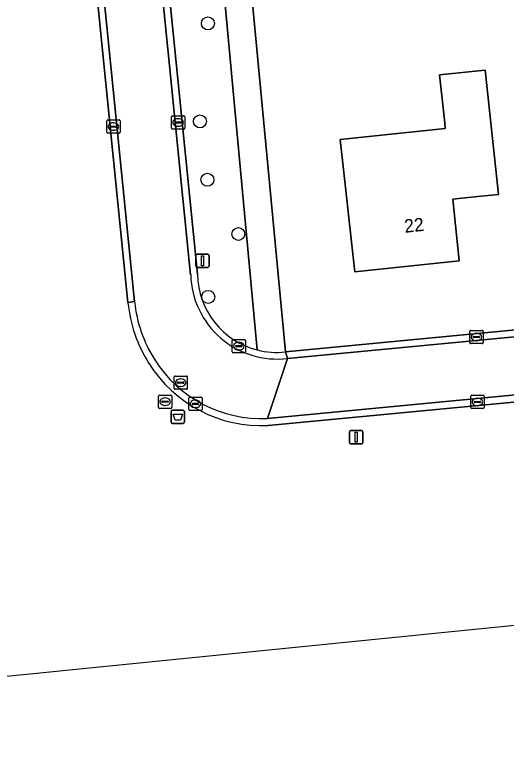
# Model space of a CAD drawing. Extents: x 162661 to 163484, y 380247 to 381230.
# Drawn here: x 162921.2 to 162958.2, y 380249 to 380305.3 of the extents above; entities that cross this region are included whole.
import ezdxf

# ---------------------------------------------------------------- set-up
doc = ezdxf.new("R2010")
doc.units = 0
for name, color, linetype in [('IMGEO_Afvalbak', 7, 'Continuous'), ('IMGEO_Boom', 7, 'Continuous'), ('IMGEO_Erf', 7, 'Continuous'), ('IMGEO_Gemengd_bos', 7, 'Continuous'), ('IMGEO_Groenvoorziening', 7, 'Continuous'), ('IMGEO_Kolk', 7, 'Continuous'), ('IMGEO_Lichtmast', 7, 'Continuous'), ('IMGEO_Pand', 7, 'Continuous'), ('IMGEO_Pand_nummerreeks', 7, 'Continuous'), ('IMGEO_Rijbaan_lokaal_gesloten', 7, 'Continuous'), ('IMGEO_Rijbaan_lokaal_open', 7, 'Continuous'), ('IMGEO_Rioolput', 7, 'Continuous'), ('IMGEO_Voetpad_open', 7, 'Continuous')]:
    doc.layers.add(name, color=color, linetype=linetype)

msp = doc.modelspace()

# ---------------------------------------------------------------- linework, layer by layer
at = {"layer": 'IMGEO_Afvalbak'}
for p, q in [((162932.953, 380274.682), (162932.953, 380275.482)), ((162932.953, 380275.482), (162932.953, 380274.682)), ((162933.053, 380275.582), (162933.843, 380275.582)), ((162933.843, 380275.582), (162933.053, 380275.582)), ((162933.943, 380275.482), (162933.943, 380274.682)), ((162933.943, 380274.682), (162933.943, 380275.482)), ((162933.843, 380274.582), (162933.053, 380274.582)), ((162933.053, 380274.582), (162933.843, 380274.582))]:
    msp.add_line(p, q, dxfattribs=at)
msp.add_lwpolyline([(162933.096, 380275.296), (162933.8, 380275.296), (162933.651, 380274.826), (162933.245, 380274.826), (162933.096, 380275.296)], dxfattribs=at)
for centre, start, end in [((162933.053, 380275.482), 90, 180), ((162933.053, 380275.482), 90, 180), ((162933.843, 380275.482), 0, 90), ((162933.843, 380275.482), 360, 90), ((162933.053, 380274.682), 180, 270), ((162933.053, 380274.682), 180, 270), ((162933.843, 380274.682), 270, 0), ((162933.843, 380274.682), 270, 0)]:
    msp.add_arc(centre, 0.1, start, end, dxfattribs=at)
at = {"layer": 'IMGEO_Boom'}
for centre in [(162935.717, 380304.705), (162935.116, 380297.327), (162935.674, 380292.93), (162938.006, 380288.849), (162935.738, 380284.117)]:
    msp.add_circle(centre, 0.489, dxfattribs=at)
at = {"layer": 'IMGEO_Erf'}
for points in [[(163025.144, 380326.321), (163024.481, 380337.057), (163009.587, 380336.032), (163009.593, 380335.742), (163006.725, 380335.529), (163006.73, 380335.638), (163003.141, 380335.415), (163000, 380335.199), (162936.743, 380330.858), (162941.559, 380279.973), (163028.489, 380288.289)], [(162953.584, 380296.784), (162953.537, 380297.227), (162953.157, 380300.828), (162956.592, 380301.19), (162956.715, 380300.025), (162957.582, 380291.83), (162955.998, 380291.663), (162954.146, 380291.468), (162954.636, 380286.834), (162946.769, 380286.004), (162945.669, 380295.974)]]:
    msp.add_lwpolyline(points, close=True, dxfattribs=at)
at = {"layer": 'IMGEO_Gemengd_bos'}
for points in [[(162929.701, 380283.683), (162923.037, 380349.9)], [(162854.54, 380248.952), (162974.798, 380261.009), (163143.705, 380286.144), (163143.702, 380286.229), (163143.673, 380287.21), (163143.37, 380289.928), (163142.476, 380293.987)], [(163020.214, 380282.048), (162940.242, 380274.439)]]:
    msp.add_lwpolyline(points, dxfattribs=at)
for centre, radius, start, end in [((162939.967, 380284.67), 10.314, 185.4904, 212.594), ((162939.73, 380284.389), 9.963, 211.9674, 272.9458)]:
    msp.add_arc(centre, radius, start, end, dxfattribs=at)
at = {"layer": 'IMGEO_Groenvoorziening'}
msp.add_lwpolyline([(162939.426, 380280.12), (162934.723, 380330.738), (162930.435, 380330.4), (162934.938, 380285.824)], dxfattribs=at)
msp.add_arc((162940.899, 380285.896), 5.961, 180.6944, 255.6981, dxfattribs=at)
at = {"layer": 'IMGEO_Kolk'}
for p, q in [((162928.102, 380296.509), (162928.102, 380297.361)), ((162928.177, 380297.435), (162929.029, 380297.435)), ((162929.103, 380297.361), (162929.103, 380296.509)), ((162932.971, 380296.82), (162932.971, 380297.672)), ((162933.046, 380297.746), (162933.898, 380297.746)), ((162933.273, 380297.289), (162933.671, 380297.289)), ((162933.459, 380297.526), (162933.484, 380297.526)), ((162933.972, 380297.672), (162933.972, 380296.82)), ((162928.361, 380296.929), (162928.361, 380296.941)), ((162928.799, 380296.892), (162928.401, 380296.892)), ((162928.404, 380296.978), (162928.802, 380296.978)), ((162928.59, 380297.215), (162928.615, 380297.215)), ((162928.845, 380296.941), (162928.845, 380296.929)), ((162933.898, 380296.746), (162933.046, 380296.746)), ((162933.23, 380297.24), (162933.23, 380297.252)), ((162933.668, 380297.203), (162933.27, 380297.203)), ((162933.482, 380296.966), (162933.457, 380296.966)), ((162933.714, 380297.252), (162933.714, 380297.24)), ((162929.029, 380296.435), (162928.177, 380296.435)), ((162928.613, 380296.655), (162928.588, 380296.655)), ((162955.427, 380280.67), (162955.427, 380281.522)), ((162955.502, 380281.596), (162956.354, 380281.596)), ((162956.428, 380281.522), (162956.428, 380280.67)), ((162955.686, 380281.09), (162955.686, 380281.102)), ((162956.124, 380281.053), (162955.726, 380281.053)), ((162955.729, 380281.139), (162956.127, 380281.139)), ((162955.915, 380281.376), (162955.94, 380281.376)), ((162956.17, 380281.102), (162956.17, 380281.09)), ((162937.543, 380279.981), (162937.543, 380280.833)), ((162937.618, 380280.907), (162938.47, 380280.907)), ((162937.802, 380280.401), (162937.802, 380280.413)), ((162938.24, 380280.364), (162937.842, 380280.364)), ((162937.845, 380280.45), (162938.243, 380280.45)), ((162938.031, 380280.687), (162938.056, 380280.687)), ((162938.286, 380280.413), (162938.286, 380280.401)), ((162938.544, 380280.833), (162938.544, 380279.981)), ((162956.354, 380280.596), (162955.502, 380280.596)), ((162955.938, 380280.816), (162955.913, 380280.816)), ((162938.47, 380279.907), (162937.618, 380279.907)), ((162938.054, 380280.127), (162938.029, 380280.127)), ((162934.271, 380275.635), (162934.271, 380276.487)), ((162934.346, 380276.561), (162935.198, 380276.561)), ((162935.272, 380276.487), (162935.272, 380275.635)), ((162955.498, 380275.78), (162955.498, 380276.632)), ((162955.573, 380276.706), (162956.425, 380276.706)), ((162955.986, 380276.486), (162956.011, 380276.486)), ((162956.499, 380276.632), (162956.499, 380275.78)), ((162934.53, 380276.055), (162934.53, 380276.067)), ((162934.968, 380276.018), (162934.57, 380276.018)), ((162934.573, 380276.104), (162934.971, 380276.104)), ((162934.759, 380276.341), (162934.784, 380276.341)), ((162935.014, 380276.067), (162935.014, 380276.055)), ((162955.757, 380276.2), (162955.757, 380276.212)), ((162956.195, 380276.163), (162955.797, 380276.163)), ((162955.8, 380276.249), (162956.198, 380276.249)), ((162956.009, 380275.926), (162955.984, 380275.926)), ((162956.241, 380276.212), (162956.241, 380276.2)), ((162935.198, 380275.561), (162934.346, 380275.561)), ((162934.782, 380275.781), (162934.757, 380275.781)), ((162956.425, 380275.706), (162955.573, 380275.706))]:
    msp.add_line(p, q, dxfattribs=at)
for points in [[(162928.102, 380296.509), (162928.102, 380297.361)], [(162928.177, 380297.435), (162929.029, 380297.435)], [(162929.103, 380297.361), (162929.103, 380296.509)], [(162932.971, 380296.82), (162932.971, 380297.672)], [(162933.046, 380297.746), (162933.898, 380297.746)], [(162933.972, 380297.672), (162933.972, 380296.82)], [(162933.898, 380296.746), (162933.046, 380296.746)], [(162929.029, 380296.435), (162928.177, 380296.435)], [(162955.427, 380280.67), (162955.427, 380281.522)], [(162955.502, 380281.596), (162956.354, 380281.596)], [(162956.428, 380281.522), (162956.428, 380280.67)], [(162937.543, 380279.981), (162937.543, 380280.833)], [(162937.618, 380280.907), (162938.47, 380280.907)], [(162938.544, 380280.833), (162938.544, 380279.981)], [(162956.354, 380280.596), (162955.502, 380280.596)], [(162938.47, 380279.907), (162937.618, 380279.907)], [(162934.271, 380275.635), (162934.271, 380276.487)], [(162934.346, 380276.561), (162935.198, 380276.561)], [(162935.272, 380276.487), (162935.272, 380275.635)], [(162955.498, 380275.78), (162955.498, 380276.632)], [(162955.573, 380276.706), (162956.425, 380276.706)], [(162956.499, 380276.632), (162956.499, 380275.78)], [(162935.198, 380275.561), (162934.346, 380275.561)], [(162956.425, 380275.706), (162955.573, 380275.706)]]:
    msp.add_lwpolyline(points, dxfattribs=at)
for centre, radius, start, end in [((162928.179, 380297.359), 0.0765, 91.552, 178.448), ((162928.179, 380297.359), 0.0765, 91.552, 178.448), ((162929.027, 380297.359), 0.0765, 1.552, 88.448), ((162929.027, 380297.359), 0.0765, 1.552, 88.448), ((162933.048, 380297.67), 0.0765, 91.552, 178.448), ((162933.048, 380297.67), 0.0765, 91.552, 178.448), ((162933.27, 380297.249), 0.0403, 85.8775, 175.7526), ((162933.675, 380297.251), 0.0386, 1.7309, 96.639), ((162933.896, 380297.67), 0.0765, 1.552, 88.448), ((162933.896, 380297.67), 0.0765, 1.552, 88.448), ((162928.401, 380296.938), 0.0403, 85.8775, 175.7526), ((162928.398, 380296.928), 0.0366, 178.938, 274.7102), ((162928.802, 380296.935), 0.043, 264.8664, 352.4533), ((162928.806, 380296.94), 0.0386, 1.7309, 96.639), ((162933.048, 380296.822), 0.0765, 181.552, 268.448), ((162933.048, 380296.822), 0.0765, 181.552, 268.448), ((162933.267, 380297.239), 0.0366, 178.938, 274.7102), ((162933.671, 380297.246), 0.043, 264.8664, 352.4533), ((162933.896, 380296.822), 0.0765, 271.552, 358.448), ((162933.896, 380296.822), 0.0765, 271.552, 358.448), ((162928.179, 380296.511), 0.0765, 181.552, 268.448), ((162928.179, 380296.511), 0.0765, 181.552, 268.448), ((162929.027, 380296.511), 0.0765, 271.552, 358.448), ((162929.027, 380296.511), 0.0765, 271.552, 358.448), ((162955.504, 380281.52), 0.0765, 91.552, 178.448), ((162955.504, 380281.52), 0.0765, 91.552, 178.448), ((162956.352, 380281.52), 0.0765, 1.552, 88.448), ((162956.352, 380281.52), 0.0765, 1.552, 88.448), ((162955.726, 380281.099), 0.0403, 85.8775, 175.7526), ((162955.723, 380281.089), 0.0366, 178.938, 274.7102), ((162956.127, 380281.096), 0.043, 264.8664, 352.4533), ((162956.131, 380281.101), 0.0386, 1.7309, 96.639), ((162937.62, 380280.831), 0.0765, 91.552, 178.448), ((162937.62, 380280.831), 0.0765, 91.552, 178.448), ((162937.842, 380280.41), 0.0403, 85.8775, 175.7526), ((162937.839, 380280.4), 0.0366, 178.938, 274.7102), ((162938.243, 380280.407), 0.043, 264.8664, 352.4533), ((162938.247, 380280.412), 0.0386, 1.7309, 96.639), ((162938.468, 380280.831), 0.0765, 1.552, 88.448), ((162938.468, 380280.831), 0.0765, 1.552, 88.448), ((162955.504, 380280.672), 0.0765, 181.552, 268.448), ((162955.504, 380280.672), 0.0765, 181.552, 268.448), ((162956.352, 380280.672), 0.0765, 271.552, 358.448), ((162956.352, 380280.672), 0.0765, 271.552, 358.448), ((162937.62, 380279.983), 0.0765, 181.552, 268.448), ((162937.62, 380279.983), 0.0765, 181.552, 268.448), ((162938.468, 380279.983), 0.0765, 271.552, 358.448), ((162938.468, 380279.983), 0.0765, 271.552, 358.448), ((162934.348, 380276.485), 0.0765, 91.552, 178.448), ((162934.348, 380276.485), 0.0765, 91.552, 178.448), ((162935.196, 380276.485), 0.0765, 1.552, 88.448), ((162935.196, 380276.485), 0.0765, 1.552, 88.448), ((162955.575, 380276.63), 0.0765, 91.552, 178.448), ((162955.575, 380276.63), 0.0765, 91.552, 178.448), ((162956.423, 380276.63), 0.0765, 1.552, 88.448), ((162956.423, 380276.63), 0.0765, 1.552, 88.448), ((162934.57, 380276.064), 0.0403, 85.8775, 175.7526), ((162934.567, 380276.054), 0.0366, 178.938, 274.7102), ((162934.971, 380276.061), 0.043, 264.8664, 352.4533), ((162934.975, 380276.066), 0.0386, 1.7309, 96.639), ((162955.797, 380276.209), 0.0403, 85.8775, 175.7526), ((162955.794, 380276.199), 0.0366, 178.938, 274.7102), ((162956.198, 380276.206), 0.043, 264.8664, 352.4533), ((162956.202, 380276.211), 0.0386, 1.7309, 96.639), ((162934.348, 380275.637), 0.0765, 181.552, 268.448), ((162934.348, 380275.637), 0.0765, 181.552, 268.448), ((162935.196, 380275.637), 0.0765, 271.552, 358.448), ((162935.196, 380275.637), 0.0765, 271.552, 358.448), ((162955.575, 380275.782), 0.0765, 181.552, 268.448), ((162955.575, 380275.782), 0.0765, 181.552, 268.448), ((162956.423, 380275.782), 0.0765, 271.552, 358.448), ((162956.423, 380275.782), 0.0765, 271.552, 358.448)]:
    msp.add_arc(centre, radius, start, end, dxfattribs=at)
for centre, major_axis, ratio, start_param, end_param in [((162933.458, 380297.246), (-0.387, 0.002), 0.722429, 4.712389, 7.853982), ((162933.483, 380297.246), (-0.39, 0.002), 0.717154, 1.570796, 4.712389), ((162928.589, 380296.935), (-0.387, 0.002), 0.722429, 4.712389, 7.853982), ((162928.614, 380296.935), (-0.39, 0.002), 0.717154, 1.570796, 4.712389), ((162955.914, 380281.096), (-0.387, 0.002), 0.722429, 4.712389, 7.853982), ((162955.939, 380281.096), (-0.39, 0.002), 0.717154, 1.570796, 4.712389), ((162938.03, 380280.407), (-0.387, 0.002), 0.722429, 4.712389, 7.853982), ((162938.055, 380280.407), (-0.39, 0.002), 0.717154, 1.570796, 4.712389), ((162955.985, 380276.206), (-0.387, 0.002), 0.722429, 4.712389, 7.853982), ((162956.01, 380276.206), (-0.39, 0.002), 0.717154, 1.570796, 4.712389), ((162934.758, 380276.061), (-0.387, 0.002), 0.722429, 4.712389, 7.853982), ((162934.783, 380276.061), (-0.39, 0.002), 0.717154, 1.570796, 4.712389)]:
    msp.add_ellipse(centre, major_axis=major_axis, ratio=ratio, start_param=start_param, end_param=end_param, dxfattribs=at)
at = {"layer": 'IMGEO_Lichtmast'}
for p, q in [((162934.812, 380286.44), (162934.812, 380287.24)), ((162934.812, 380287.24), (162934.812, 380286.44)), ((162934.912, 380287.34), (162935.702, 380287.34)), ((162935.702, 380287.34), (162934.912, 380287.34)), ((162935.802, 380287.24), (162935.802, 380286.44)), ((162935.802, 380286.44), (162935.802, 380287.24)), ((162935.702, 380286.34), (162934.912, 380286.34)), ((162934.912, 380286.34), (162935.702, 380286.34)), ((162946.38, 380273.157), (162946.38, 380273.957)), ((162946.38, 380273.957), (162946.38, 380273.157)), ((162946.48, 380274.057), (162947.27, 380274.057)), ((162947.27, 380274.057), (162946.48, 380274.057)), ((162947.37, 380273.957), (162947.37, 380273.157)), ((162947.37, 380273.157), (162947.37, 380273.957)), ((162947.27, 380273.057), (162946.48, 380273.057)), ((162946.48, 380273.057), (162947.27, 380273.057))]:
    msp.add_line(p, q, dxfattribs=at)
for points in [[(162935.232, 380287.215), (162935.382, 380287.215), (162935.382, 380286.465), (162935.232, 380286.465), (162935.232, 380287.215)], [(162946.8, 380273.932), (162946.95, 380273.932), (162946.95, 380273.182), (162946.8, 380273.182), (162946.8, 380273.932)]]:
    msp.add_lwpolyline(points, dxfattribs=at)
for centre, start, end in [((162934.912, 380287.24), 90, 180), ((162934.912, 380287.24), 90, 180), ((162935.702, 380287.24), 0, 90), ((162935.702, 380287.24), 360, 90), ((162934.912, 380286.44), 180, 270), ((162934.912, 380286.44), 180, 270), ((162935.702, 380286.44), 270, 0), ((162935.702, 380286.44), 270, 0), ((162946.48, 380273.957), 90, 180), ((162946.48, 380273.957), 90, 180), ((162947.27, 380273.957), 0, 90), ((162947.27, 380273.957), 360, 90), ((162946.48, 380273.157), 180, 270), ((162946.48, 380273.157), 180, 270), ((162947.27, 380273.157), 270, 0), ((162947.27, 380273.157), 270, 0)]:
    msp.add_arc(centre, 0.1, start, end, dxfattribs=at)
at = {"layer": 'IMGEO_Pand'}
msp.add_lwpolyline([(162953.584, 380296.784), (162945.669, 380295.974), (162946.769, 380286.004), (162954.636, 380286.834), (162954.146, 380291.468), (162955.998, 380291.663), (162957.582, 380291.83), (162956.715, 380300.025), (162956.592, 380301.19), (162953.157, 380300.828), (162953.537, 380297.227)], close=True, dxfattribs=at)
at = {"layer": 'IMGEO_Rijbaan_lokaal_gesloten'}
for points in [[(162923.534, 380349.958), (162924.07, 380344.676), (162930.197, 380283.765)], [(162934.418, 380285.771), (162929.325, 380336.523)], [(163034.368, 380286.84), (163032.785, 380288.167), (162941.711, 380279.483), (162940.195, 380274.962), (163021.508, 380282.709)], [(162940.195, 380274.962), (162941.711, 380279.483)]]:
    msp.add_lwpolyline(points, dxfattribs=at)
for centre, radius, start, end in [((162940.932, 380285.952), 6.516, 181.5957, 276.8687), ((162940.199, 380284.762), 10.051, 185.6915, 212.4409), ((162939.761, 380284.485), 9.533, 212.4512, 272.6115)]:
    msp.add_arc(centre, radius, start, end, dxfattribs=at)
at = {"layer": 'IMGEO_Rijbaan_lokaal_open'}
for points in [[(162923.037, 380349.9), (162929.701, 380283.683), (162930.197, 380283.765), (162924.07, 380344.676), (162923.534, 380349.958)], [(162929.325, 380336.523), (162934.418, 380285.771)], [(162934.938, 380285.824), (162930.435, 380330.4)], [(163031.404, 380288.568), (163030.282, 380288.461), (163028.489, 380288.289), (162941.559, 380279.973), (162941.711, 380279.483), (163032.785, 380288.167)], [(162930.197, 380283.765), (162929.701, 380283.683)], [(163021.508, 380282.709), (162940.195, 380274.962)], [(162940.242, 380274.439), (163020.214, 380282.048)], [(162941.711, 380279.483), (162941.559, 380279.973)]]:
    msp.add_lwpolyline(points, dxfattribs=at)
for centre, radius, start, end in [((162940.932, 380285.952), 6.516, 181.5957, 276.8687), ((162940.899, 380285.896), 5.961, 180.6944, 255.6981), ((162940.199, 380284.762), 10.051, 185.6915, 212.4409), ((162939.967, 380284.67), 10.314, 185.4904, 212.594), ((162940.895, 380285.892), 5.956, 255.7183, 276.3969), ((162939.761, 380284.485), 9.533, 212.4512, 272.6115), ((162939.73, 380284.389), 9.963, 211.9674, 272.9458)]:
    msp.add_arc(centre, radius, start, end, dxfattribs=at)
at = {"layer": 'IMGEO_Rioolput'}
for p, q in [((162933.241, 380278.16), (162934.093, 380278.16)), ((162933.166, 380277.234), (162933.166, 380278.086)), ((162933.425, 380277.654), (162933.425, 380277.666)), ((162933.863, 380277.617), (162933.465, 380277.617)), ((162933.468, 380277.703), (162933.866, 380277.703)), ((162933.654, 380277.94), (162933.679, 380277.94)), ((162933.909, 380277.666), (162933.909, 380277.654)), ((162934.167, 380278.086), (162934.167, 380277.234)), ((162934.093, 380277.16), (162933.241, 380277.16)), ((162933.677, 380277.38), (162933.652, 380277.38)), ((162931.994, 380275.799), (162931.994, 380276.651)), ((162932.069, 380276.725), (162932.921, 380276.725)), ((162932.482, 380276.505), (162932.507, 380276.505)), ((162932.995, 380276.651), (162932.995, 380275.799)), ((162932.253, 380276.219), (162932.253, 380276.231)), ((162932.691, 380276.182), (162932.293, 380276.182)), ((162932.296, 380276.268), (162932.694, 380276.268)), ((162932.505, 380275.945), (162932.48, 380275.945)), ((162932.737, 380276.231), (162932.737, 380276.219)), ((162932.921, 380275.725), (162932.069, 380275.725))]:
    msp.add_line(p, q, dxfattribs=at)
for points in [[(162933.241, 380278.16), (162934.093, 380278.16)], [(162933.166, 380277.234), (162933.166, 380278.086)], [(162934.167, 380278.086), (162934.167, 380277.234)], [(162934.093, 380277.16), (162933.241, 380277.16)], [(162931.994, 380275.799), (162931.994, 380276.651)], [(162932.069, 380276.725), (162932.921, 380276.725)], [(162932.995, 380276.651), (162932.995, 380275.799)], [(162932.921, 380275.725), (162932.069, 380275.725)]]:
    msp.add_lwpolyline(points, dxfattribs=at)
for centre, radius, start, end in [((162933.243, 380278.084), 0.0765, 91.552, 178.448), ((162933.243, 380278.084), 0.0765, 91.552, 178.448), ((162934.091, 380278.084), 0.0765, 1.552, 88.448), ((162934.091, 380278.084), 0.0765, 1.552, 88.448), ((162933.465, 380277.663), 0.0403, 85.8775, 175.7526), ((162933.462, 380277.653), 0.0366, 178.938, 274.7102), ((162933.866, 380277.66), 0.043, 264.8664, 352.4533), ((162933.87, 380277.665), 0.0386, 1.7309, 96.639), ((162933.243, 380277.236), 0.0765, 181.552, 268.448), ((162933.243, 380277.236), 0.0765, 181.552, 268.448), ((162934.091, 380277.236), 0.0765, 271.552, 358.448), ((162934.091, 380277.236), 0.0765, 271.552, 358.448), ((162932.071, 380276.649), 0.0765, 91.552, 178.448), ((162932.071, 380276.649), 0.0765, 91.552, 178.448), ((162932.919, 380276.649), 0.0765, 1.552, 88.448), ((162932.919, 380276.649), 0.0765, 1.552, 88.448), ((162932.293, 380276.228), 0.0403, 85.8775, 175.7526), ((162932.29, 380276.218), 0.0366, 178.938, 274.7102), ((162932.694, 380276.225), 0.043, 264.8664, 352.4533), ((162932.698, 380276.23), 0.0386, 1.7309, 96.639), ((162932.071, 380275.801), 0.0765, 181.552, 268.448), ((162932.071, 380275.801), 0.0765, 181.552, 268.448), ((162932.919, 380275.801), 0.0765, 271.552, 358.448), ((162932.919, 380275.801), 0.0765, 271.552, 358.448)]:
    msp.add_arc(centre, radius, start, end, dxfattribs=at)
for centre, major_axis, ratio, start_param, end_param in [((162933.653, 380277.66), (-0.387, 0.002), 0.722429, 4.712389, 7.853982), ((162933.678, 380277.66), (-0.39, 0.002), 0.717154, 1.570796, 4.712389), ((162932.481, 380276.225), (-0.387, 0.002), 0.722429, 4.712389, 7.853982), ((162932.506, 380276.225), (-0.39, 0.002), 0.717154, 1.570796, 4.712389)]:
    msp.add_ellipse(centre, major_axis=major_axis, ratio=ratio, start_param=start_param, end_param=end_param, dxfattribs=at)
at = {"layer": 'IMGEO_Voetpad_open'}
for points in [[(162936.743, 380330.858), (162934.723, 380330.738), (162939.426, 380280.12)], [(162941.559, 380279.973), (162936.743, 380330.858)]]:
    msp.add_lwpolyline(points, dxfattribs=at)
msp.add_arc((162940.895, 380285.892), 5.956, 255.7183, 276.3969, dxfattribs=at)

# ---------------------------------------------------------------- texts
at = {"layer": 'IMGEO_Pand_nummerreeks'}
msp.add_text('22', height=1, rotation=6.0218, dxfattribs=at).set_placement((162950.54, 380288.936))

doc.saveas('drawing.dxf')
